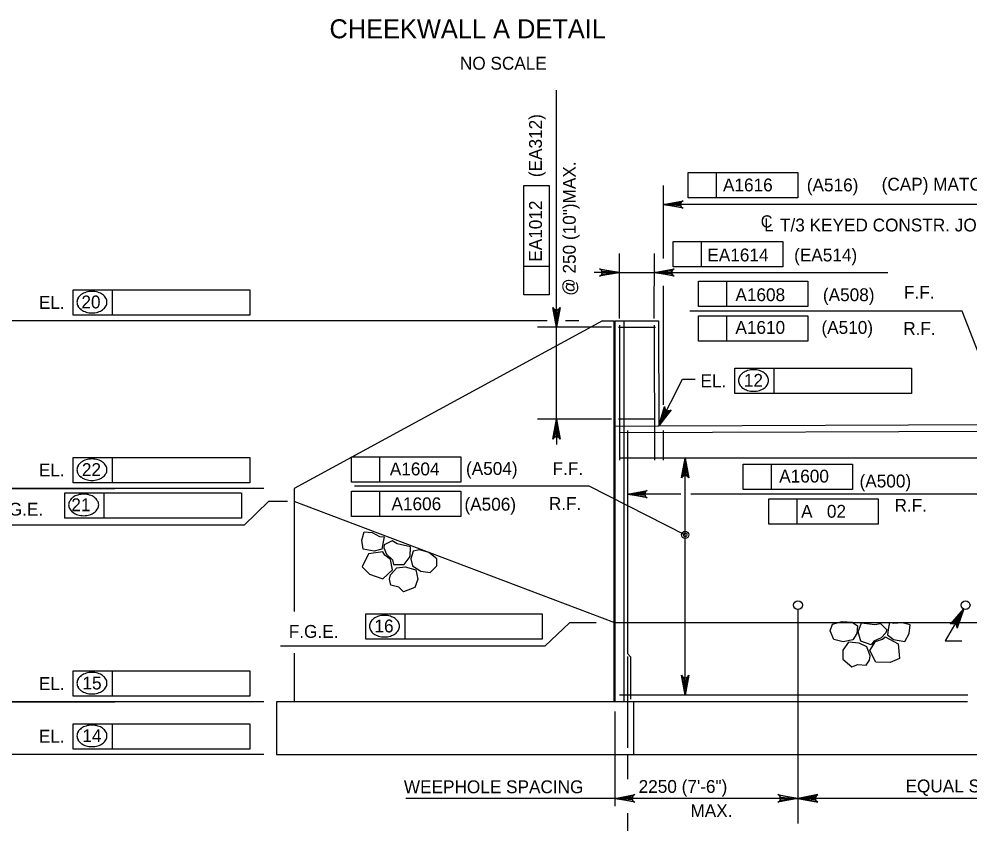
# Model space of a CAD drawing. Extents: x 634540 to 640306, y 296059 to 300275.
# Drawn here: x 638514.3 to 638736.3, y 297928.8 to 298116.7 of the extents above; entities that cross this region are included whole.
import ezdxf

# ---------------------------------------------------------------- set-up
doc = ezdxf.new("R2010")
doc.units = 0
for name, color, linetype in [('1', 7, 'Continuous'), ('10', 7, 'Continuous'), ('3', 7, 'Continuous'), ('4', 7, 'Continuous'), ('5', 7, 'Continuous')]:
    doc.layers.add(name, color=color, linetype=linetype)

# ---------------------------------------------------------------- blocks, each defined once
blk = doc.blocks.new('ROCK')
at = {"layer": '4'}
for points in [[(2.36725, 1.088), (2.2065, 0.82625), (2.378625, 0.506625), (2.66975, 0.3095), (3.128875, 0.403375), (3.48475, 0.6775), (3.4915, 1.123375), (3.25625, 1.36725), (2.783625, 1.308375)], [(1.10175, -0.02725), (1.4015, -0.159125), (1.78825, -0.148875), (1.980875, -0.266), (2.343375, 0.09475), (2.27875, 0.5505), (1.969375, 0.883), (1.4225, 0.553625), (1.152875, 0.479), (1.0105, 0.082)], [(0.74675, 0.359875), (0.882, 0.16), (1.072875, -0.144), (0.892, -0.457375), (0.448125, -0.758625), (0.1, -0.49325), (-0.095, -0.146375), (0.202875, 0.1025), (0.579125, 0.219875)], [(2.231375, -0.71725), (2.2025, -0.266375), (2.45475, 0.037125), (2.9085, 0.28875), (3.2995, 0.047625), (3.46875, -0.344), (3.231625, -0.855), (2.92, -0.860375), (2.5765, -1.054625), (2.340375, -0.904375)], [(1.2085, -0.192875), (0.778375, -0.737625), (1.008375, -1.391375), (1.48725, -1.396875), (2.09825, -1.106625), (2.133375, -0.486375), (1.723125, -0.203375), (1.37425, -0.239875)]]:
    blk.add_lwpolyline(points, close=True, dxfattribs=at)
blk = doc.blocks.new('V')
at = {"layer": '1'}
blk.add_line((0, 0), (0, 0), dxfattribs=at)

msp = doc.modelspace()

# ---------------------------------------------------------------- linework, layer by layer
at = {"layer": '10'}
for p, q in [((638650.47, 298046.26), (638578.54, 298007.13)), ((638650.47, 298046.26), (638653.13, 298046.26)), ((638653.13, 298046.26), (638653.13, 297957.3)), ((638653.35, 298046.26), (638653.35, 297957.3)), ((638653.35, 298046.26), (638663.6, 298046.26)), ((638655.46, 298046.26), (638655.49, 297957.3)), ((638663.6, 298046.26), (638663.63, 298021.71)), ((638663.63, 298021.71), (638880.68, 298022.64)), ((638653.47, 298021.67), (638663.63, 298021.71)), ((638578.54, 298007.13), (638578.54, 297978.4)), ((638653.35, 297975.76), (638578.54, 298004.06)), ((638672.95, 297975.76), (638653.47, 297975.76)), ((638882.32, 297975.76), (638672.95, 297975.76)), ((638578.54, 297968.64), (638578.54, 297957.3)), ((638574.44, 297957.3), (638574.44, 297945)), ((638735.66, 297957.3), (638574.44, 297957.3)), ((638657.74, 297957.3), (638657.74, 297945)), ((638574.44, 297945), (638955.68, 297945))]:
    msp.add_line(p, q, dxfattribs=at)
at = {"layer": '3'}
for p, q in [((638639.77, 298050.63), (638639.77, 298100.09)), ((638670.53, 298080.88), (638696.07, 298080.88)), ((638670.53, 298074.98), (638670.53, 298080.88)), ((638677.13, 298074.98), (638677.13, 298080.88)), ((638696.07, 298080.88), (638696.07, 298074.98)), ((638632.17, 298052.31), (638632.17, 298077.85)), ((638632.17, 298077.85), (638638.07, 298077.85)), ((638638.07, 298077.85), (638638.07, 298052.31)), ((638664.66, 298077.85), (638664.66, 298060.79)), ((638769.74, 298073.41), (638664.66, 298073.41)), ((638696.07, 298074.98), (638670.53, 298074.98)), ((638667.01, 298064.76), (638692.55, 298064.76)), ((638667.01, 298058.86), (638667.01, 298064.76)), ((638673.61, 298058.86), (638673.61, 298064.76)), ((638692.55, 298064.76), (638692.55, 298058.86)), ((638654.46, 298046.77), (638654.49, 298061.95)), ((638662.57, 298046.77), (638662.6, 298061.95)), ((638638.07, 298058.9), (638632.17, 298058.9)), ((638692.55, 298058.86), (638667.01, 298058.86)), ((638654.48, 298057.52), (638648.59, 298057.52)), ((638654.49, 298057.52), (638662.6, 298057.52)), ((638662.59, 298057.52), (638717.09, 298057.52)), ((638665.56, 298057.52), (638668.51, 298057.52)), ((638526.97, 298053.45), (638536.14, 298053.45)), ((638526.97, 298047.54), (638526.97, 298053.45)), ((638536.14, 298047.54), (638536.14, 298053.45)), ((638536.14, 298053.45), (638568.18, 298053.45)), ((638568.18, 298053.45), (638568.18, 298047.54)), ((638664.66, 298054.4), (638664.66, 298026.66)), ((638672.88, 298055.48), (638698.42, 298055.48)), ((638672.88, 298049.57), (638672.88, 298055.48)), ((638679.48, 298049.57), (638679.48, 298055.48)), ((638698.42, 298055.48), (638698.42, 298049.57)), ((638638.07, 298052.31), (638632.17, 298052.31)), ((638639.77, 298047.68), (638639.77, 298050.63)), ((638698.42, 298049.57), (638672.88, 298049.57)), ((638568.18, 298047.54), (638526.97, 298047.54)), ((638734.44, 298048.48), (638670.87, 298048.48)), ((638672.88, 298047.4), (638698.42, 298047.4)), ((638672.88, 298041.49), (638672.88, 298047.4)), ((638679.48, 298041.49), (638679.48, 298047.4)), ((638698.42, 298047.4), (638698.42, 298041.49)), ((638745.29, 298020.52), (638734.44, 298048.48)), ((638637.57, 298046.26), (638483.42, 298046.26)), ((638536.87, 298046.26), (638497.32, 298046.26)), ((638652.58, 298044.72), (638635.34, 298044.72)), ((638639.77, 298023.25), (638639.77, 298044.72)), ((638644.94, 298046.26), (638641.83, 298046.26)), ((638698.42, 298041.49), (638672.88, 298041.49)), ((638681.38, 298035.15), (638690.55, 298035.15)), ((638681.38, 298029.25), (638681.38, 298035.15)), ((638690.55, 298029.25), (638690.55, 298035.15)), ((638690.55, 298035.15), (638722.59, 298035.15)), ((638722.59, 298035.15), (638722.59, 298029.25)), ((638663.63, 298021.71), (638669.19, 298032.64)), ((638669.19, 298032.64), (638672.14, 298032.64)), ((638722.59, 298029.25), (638681.38, 298029.25)), ((638652.58, 298023.25), (638635.34, 298023.25)), ((638639.77, 298020.3), (638639.77, 298017.34)), ((638526.97, 298014.32), (638536.14, 298014.32)), ((638526.97, 298008.42), (638526.97, 298014.32)), ((638536.14, 298008.42), (638536.14, 298014.32)), ((638536.14, 298014.32), (638568.18, 298014.32)), ((638568.18, 298014.32), (638568.18, 298008.42)), ((638591.9, 298014.52), (638617.44, 298014.52)), ((638591.9, 298008.61), (638591.9, 298014.52)), ((638598.5, 298008.61), (638598.5, 298014.52)), ((638617.44, 298014.52), (638617.44, 298008.61)), ((638669.79, 297958.84), (638669.79, 298014.21)), ((638683.35, 298012.78), (638708.88, 298012.78)), ((638683.35, 298006.87), (638683.35, 298012.78)), ((638689.94, 298006.87), (638689.94, 298012.78)), ((638708.88, 298012.78), (638708.88, 298006.87)), ((638571.45, 298007.13), (638492.14, 298007.13)), ((638536.87, 298007.13), (638497.32, 298007.13)), ((638543.27, 298007.13), (638497.32, 298007.13)), ((638501.17, 298007.13), (638536.69, 298007.13)), ((638568.18, 298008.42), (638526.97, 298008.42)), ((638617.44, 298008.61), (638591.9, 298008.61)), ((638592.58, 298007.74), (638647.34, 298007.74)), ((638647.34, 298007.74), (638669.79, 297996.26)), ((638708.88, 298006.87), (638683.35, 298006.87)), ((638525.03, 298000.2), (638525.03, 298006.1)), ((638525.03, 298006.1), (638534.21, 298006.1)), ((638534.21, 298000.2), (638534.21, 298006.1)), ((638534.21, 298006.1), (638566.07, 298006.1)), ((638566.24, 298006.1), (638566.24, 298000.2)), ((638591.9, 298000.53), (638591.9, 298006.44)), ((638591.9, 298006.44), (638617.44, 298006.44)), ((638598.5, 298000.53), (638598.5, 298006.44)), ((638617.44, 298006.44), (638617.44, 298000.53)), ((638668.78, 298005.78), (638656.3, 298005.78)), ((638770.61, 298005.78), (638671.08, 298005.78)), ((638689.34, 297998.79), (638689.34, 298004.69)), ((638689.34, 298004.69), (638714.87, 298004.69)), ((638695.93, 297998.79), (638695.93, 298004.69)), ((638714.87, 298004.69), (638714.87, 297998.79)), ((638572.56, 298004.06), (638566.84, 297998.55)), ((638566.24, 298000.2), (638525.03, 298000.2)), ((638617.44, 298000.53), (638591.9, 298000.53)), ((638566.84, 297998.55), (638505.82, 297998.55)), ((638714.87, 297998.79), (638689.34, 297998.79)), ((638734.83, 297978.99), (638730.48, 297971.5)), ((638595.23, 297977.81), (638604.41, 297977.81)), ((638595.23, 297971.9), (638595.23, 297977.81)), ((638604.41, 297971.9), (638604.41, 297977.81)), ((638604.41, 297977.81), (638636.45, 297977.81)), ((638636.45, 297977.81), (638636.45, 297971.9)), ((638642.76, 297975.76), (638637.05, 297970.26)), ((638649.02, 297975.76), (638642.76, 297975.76)), ((638636.45, 297971.9), (638595.23, 297971.9)), ((638730.48, 297971.5), (638734.35, 297971.5)), ((638637.05, 297970.26), (638575.36, 297970.26)), ((638526.97, 297964.49), (638536.14, 297964.49)), ((638526.97, 297958.59), (638526.97, 297964.49)), ((638536.14, 297958.59), (638536.14, 297964.49)), ((638536.14, 297964.49), (638568.18, 297964.49)), ((638568.18, 297964.49), (638568.18, 297958.59)), ((638568.18, 297958.59), (638526.97, 297958.59)), ((638571.45, 297957.3), (638483.42, 297957.3)), ((638543.27, 297957.3), (638497.32, 297957.3)), ((638501.17, 297957.3), (638536.69, 297957.3)), ((638653.35, 297955.05), (638653.35, 297932.9)), ((638526.97, 297952.19), (638536.14, 297952.19)), ((638526.97, 297946.28), (638526.97, 297952.19)), ((638536.14, 297946.28), (638536.14, 297952.19)), ((638536.14, 297952.19), (638568.18, 297952.19)), ((638568.18, 297952.19), (638568.18, 297946.28)), ((638571.45, 297945), (638483.42, 297945)), ((638568.18, 297946.28), (638526.97, 297946.28)), ((638656.3, 297945), (638656.3, 297939.23)), ((638885.79, 297934.76), (638604.59, 297934.76)), ((638656.3, 297931.32), (638656.3, 297916.35))]:
    msp.add_line(p, q, dxfattribs=at)
for points in [[(638664.66, 298073.41), (638669.32, 298074.28), (638668.96, 298074.03), (638668.77, 298073.72), (638668.72, 298073.41), (638668.77, 298073.09), (638668.96, 298072.78), (638669.32, 298072.53), (638664.66, 298073.41), (638668.96, 298072.78), (638668.77, 298073.09), (638664.66, 298073.41), (638668.72, 298073.41), (638668.77, 298073.72), (638664.66, 298073.41), (638668.96, 298074.03)], [(638654.48, 298057.52), (638649.82, 298056.64), (638650.18, 298056.89), (638650.37, 298057.21), (638650.42, 298057.52), (638650.37, 298057.83), (638650.18, 298058.14), (638649.82, 298058.39), (638654.48, 298057.52), (638650.18, 298058.14), (638650.37, 298057.83), (638654.48, 298057.52), (638650.42, 298057.52), (638650.37, 298057.21), (638654.48, 298057.52), (638650.18, 298056.89)], [(638662.59, 298057.52), (638667.25, 298058.39), (638666.9, 298058.14), (638666.71, 298057.83), (638666.66, 298057.52), (638666.71, 298057.21), (638666.9, 298056.89), (638667.25, 298056.64), (638662.59, 298057.52), (638666.9, 298056.89), (638666.71, 298057.21), (638662.59, 298057.52), (638666.66, 298057.52), (638666.71, 298057.83), (638662.59, 298057.52), (638666.9, 298058.14)], [(638639.77, 298044.72), (638638.9, 298049.38), (638639.15, 298049.03), (638639.46, 298048.84), (638639.77, 298048.79), (638640.08, 298048.84), (638640.4, 298049.03), (638640.65, 298049.38), (638639.77, 298044.72), (638640.4, 298049.03), (638640.08, 298048.84), (638639.77, 298044.72), (638639.77, 298048.79), (638639.46, 298048.84), (638639.77, 298044.72), (638639.15, 298049.03)], [(638663.63, 298021.71), (638664.97, 298026.26), (638665.03, 298025.83), (638665.22, 298025.52), (638665.47, 298025.34), (638665.78, 298025.24), (638666.14, 298025.26), (638666.52, 298025.47), (638663.63, 298021.71), (638666.14, 298025.26), (638665.78, 298025.24), (638663.63, 298021.71), (638665.47, 298025.34), (638665.22, 298025.52), (638663.63, 298021.71), (638665.03, 298025.83)], [(638639.77, 298023.25), (638640.65, 298018.59), (638640.4, 298018.95), (638640.08, 298019.13), (638639.77, 298019.18), (638639.46, 298019.13), (638639.15, 298018.95), (638638.9, 298018.59), (638639.77, 298023.25), (638639.15, 298018.95), (638639.46, 298019.13), (638639.77, 298023.25), (638639.77, 298019.18), (638640.08, 298019.13), (638639.77, 298023.25), (638640.4, 298018.95)], [(638669.79, 298014.21), (638670.66, 298009.55), (638670.42, 298009.91), (638670.1, 298010.09), (638669.79, 298010.15), (638669.48, 298010.09), (638669.17, 298009.91), (638668.92, 298009.55), (638669.79, 298014.21), (638669.17, 298009.91), (638669.48, 298010.09), (638669.79, 298014.21), (638669.79, 298010.15), (638670.1, 298010.09), (638669.79, 298014.21), (638670.42, 298009.91)], [(638656.3, 298005.78), (638660.96, 298006.65), (638660.6, 298006.4), (638660.42, 298006.09), (638660.37, 298005.78), (638660.42, 298005.47), (638660.6, 298005.15), (638660.96, 298004.9), (638656.3, 298005.78), (638660.6, 298005.15), (638660.42, 298005.47), (638656.3, 298005.78), (638660.37, 298005.78), (638660.42, 298006.09), (638656.3, 298005.78), (638660.6, 298006.4)], [(638734.83, 297978.99), (638733.25, 297974.52), (638733.21, 297974.96), (638733.03, 297975.28), (638732.79, 297975.48), (638732.49, 297975.59), (638732.13, 297975.59), (638731.73, 297975.4), (638734.83, 297978.99), (638732.13, 297975.59), (638732.49, 297975.59), (638734.83, 297978.99), (638732.79, 297975.48), (638733.03, 297975.28), (638734.83, 297978.99), (638733.21, 297974.96)], [(638669.79, 297958.84), (638668.92, 297963.5), (638669.17, 297963.14), (638669.48, 297962.96), (638669.79, 297962.91), (638670.1, 297962.96), (638670.42, 297963.14), (638670.66, 297963.5), (638669.79, 297958.84), (638670.42, 297963.14), (638670.1, 297962.96), (638669.79, 297958.84), (638669.79, 297962.91), (638669.48, 297962.96), (638669.79, 297958.84), (638669.17, 297963.14)]]:
    msp.add_lwpolyline(points, dxfattribs=at)
for points in [[(638651.54, 298058.01), (638651.54, 298057.03), (638654.49, 298057.52)], [(638665.56, 298058.01), (638665.56, 298057.03), (638662.6, 298057.52)], [(638639.28, 298047.68), (638640.27, 298047.68), (638639.77, 298044.72)], [(638664.53, 298024.57), (638665.41, 298024.12), (638663.63, 298021.71)], [(638639.28, 298020.3), (638640.27, 298020.3), (638639.77, 298023.25)], [(638670.28, 298011.26), (638669.3, 298011.26), (638669.79, 298014.21)], [(638733.78, 297976.21), (638732.93, 297976.7), (638734.84, 297979.01)], [(638670.28, 297961.8), (638669.3, 297961.8), (638669.79, 297958.84)]]:
    msp.add_lwpolyline(points, close=True, dxfattribs=at)
for centre, radius in [((638669.79, 297996.26), 0.833), ((638669.79, 297996.26), 0.417), ((638696.12, 297979.86), 1.03), ((638735.24, 297979.86), 1.03)]:
    msp.add_circle(centre, radius, dxfattribs=at)
for centre, radius, start, end in [((638529.67, 298050.6), 1.83, 149.9767, 180), ((638530.47, 298050.14), 2.76, 125.6316, 149.9767), ((638531, 298049.4), 3.66, 106.5358, 125.6316), ((638531.35, 298048.24), 4.87, 90, 106.5358), ((638531.35, 298048.24), 4.87, 73.4642, 90), ((638531.69, 298049.4), 3.66, 54.3684, 73.4642), ((638532.22, 298050.14), 2.76, 30.0233, 54.3684), ((638533.02, 298050.6), 1.83, 0, 30.0233), ((638529.67, 298050.6), 1.83, 180, 210.0233), ((638530.47, 298051.07), 2.76, 210.0233, 234.3684), ((638532.22, 298051.07), 2.76, 305.6316, 329.9767), ((638533.02, 298050.6), 1.83, 329.9767, 0), ((638531, 298051.8), 3.66, 234.3684, 253.4642), ((638531.35, 298052.96), 4.87, 253.4642, 270), ((638531.35, 298052.96), 4.87, 270, 286.5358), ((638531.69, 298051.8), 3.66, 286.5358, 305.6316), ((638684.88, 298031.84), 2.76, 125.6316, 149.9767), ((638685.41, 298031.11), 3.66, 106.5358, 125.6316), ((638685.76, 298029.95), 4.87, 90, 106.5358), ((638685.76, 298029.95), 4.87, 73.4642, 90), ((638686.1, 298031.11), 3.66, 54.3684, 73.4642), ((638686.63, 298031.84), 2.76, 30.0233, 54.3684), ((638684.08, 298032.31), 1.83, 149.9767, 180), ((638684.08, 298032.31), 1.83, 180, 210.0233), ((638684.88, 298032.77), 2.76, 210.0233, 234.3684), ((638686.63, 298032.77), 2.76, 305.6316, 329.9767), ((638687.43, 298032.31), 1.83, 0, 30.0233), ((638687.43, 298032.31), 1.83, 329.9767, 0), ((638685.41, 298033.51), 3.66, 234.3684, 253.4642), ((638685.76, 298034.67), 4.87, 253.4642, 270), ((638685.76, 298034.67), 4.87, 270, 286.5358), ((638686.1, 298033.51), 3.66, 286.5358, 305.6316), ((638531, 298010.28), 3.66, 106.5358, 125.6316), ((638531.35, 298009.12), 4.87, 90, 106.5358), ((638531.35, 298009.12), 4.87, 73.4642, 90), ((638531.69, 298010.28), 3.66, 54.3684, 73.4642), ((638529.67, 298011.48), 1.83, 149.9767, 180), ((638529.67, 298011.48), 1.83, 180, 210.0233), ((638530.47, 298011.01), 2.76, 125.6316, 149.9767), ((638532.22, 298011.01), 2.76, 30.0233, 54.3684), ((638533.02, 298011.48), 1.83, 0, 30.0233), ((638533.02, 298011.48), 1.83, 329.9767, 0), ((638530.47, 298011.94), 2.76, 210.0233, 234.3684), ((638531, 298012.68), 3.66, 234.3684, 253.4642), ((638531.35, 298013.84), 4.87, 253.4642, 270), ((638531.35, 298013.84), 4.87, 270, 286.5358), ((638531.69, 298012.68), 3.66, 286.5358, 305.6316), ((638532.22, 298011.94), 2.76, 305.6316, 329.9767), ((638528.54, 298002.79), 2.76, 125.6316, 149.9767), ((638529.07, 298002.06), 3.66, 106.5358, 125.6316), ((638529.41, 298000.9), 4.87, 90, 106.5358), ((638529.41, 298000.9), 4.87, 73.4642, 90), ((638529.75, 298002.06), 3.66, 54.3684, 73.4642), ((638530.28, 298002.79), 2.76, 30.0233, 54.3684), ((638527.73, 298003.26), 1.83, 149.9767, 180), ((638527.73, 298003.26), 1.83, 180, 210.0233), ((638531.09, 298003.26), 1.83, 0, 30.0233), ((638531.09, 298003.26), 1.83, 329.9767, 0), ((638528.54, 298003.72), 2.76, 210.0233, 234.3684), ((638529.07, 298004.46), 3.66, 234.3684, 253.4642), ((638529.41, 298005.62), 4.87, 253.4642, 270), ((638529.41, 298005.62), 4.87, 270, 286.5358), ((638529.75, 298004.46), 3.66, 286.5358, 305.6316), ((638530.28, 298003.72), 2.76, 305.6316, 329.9767), ((638597.94, 297974.96), 1.83, 149.9767, 180), ((638598.74, 297974.49), 2.76, 125.6316, 149.9767), ((638599.27, 297973.76), 3.66, 106.5358, 125.6316), ((638599.61, 297972.6), 4.87, 90, 106.5358), ((638599.61, 297972.6), 4.87, 73.4642, 90), ((638599.96, 297973.76), 3.66, 54.3684, 73.4642), ((638600.48, 297974.49), 2.76, 30.0233, 54.3684), ((638601.29, 297974.96), 1.83, 0, 30.0233), ((638597.94, 297974.96), 1.83, 180, 210.0233), ((638598.74, 297975.42), 2.76, 210.0233, 234.3684), ((638600.48, 297975.42), 2.76, 305.6316, 329.9767), ((638601.29, 297974.96), 1.83, 329.9767, 0), ((638599.27, 297976.16), 3.66, 234.3684, 253.4642), ((638599.61, 297977.32), 4.87, 253.4642, 270), ((638599.61, 297977.32), 4.87, 270, 286.5358), ((638599.96, 297976.16), 3.66, 286.5358, 305.6316), ((638529.67, 297961.65), 1.83, 149.9767, 180), ((638530.47, 297961.18), 2.76, 125.6316, 149.9767), ((638531, 297960.45), 3.66, 106.5358, 125.6316), ((638531.35, 297959.29), 4.87, 90, 106.5358), ((638531.35, 297959.29), 4.87, 73.4642, 90), ((638531.69, 297960.45), 3.66, 54.3684, 73.4642), ((638532.22, 297961.18), 2.76, 30.0233, 54.3684), ((638533.02, 297961.65), 1.83, 0, 30.0233), ((638529.67, 297961.65), 1.83, 180, 210.0233), ((638530.47, 297962.11), 2.76, 210.0233, 234.3684), ((638532.22, 297962.11), 2.76, 305.6316, 329.9767), ((638533.02, 297961.65), 1.83, 329.9767, 0), ((638531, 297962.85), 3.66, 234.3684, 253.4642), ((638531.35, 297964.01), 4.87, 253.4642, 270), ((638531.35, 297964.01), 4.87, 270, 286.5358), ((638531.69, 297962.85), 3.66, 286.5358, 305.6316), ((638531, 297948.14), 3.66, 106.5358, 125.6316), ((638531.35, 297946.98), 4.87, 90, 106.5358), ((638531.35, 297946.98), 4.87, 73.4642, 90), ((638531.69, 297948.14), 3.66, 54.3684, 73.4642), ((638529.67, 297949.34), 1.83, 149.9767, 180), ((638529.67, 297949.34), 1.83, 180, 210.0233), ((638530.47, 297948.88), 2.76, 125.6316, 149.9767), ((638532.22, 297948.88), 2.76, 30.0233, 54.3684), ((638533.02, 297949.34), 1.83, 0, 30.0233), ((638533.02, 297949.34), 1.83, 329.9767, 0), ((638530.47, 297949.81), 2.76, 210.0233, 234.3684), ((638531, 297950.54), 3.66, 234.3684, 253.4642), ((638531.35, 297951.7), 4.87, 253.4642, 270), ((638531.35, 297951.7), 4.87, 270, 286.5358), ((638531.69, 297950.54), 3.66, 286.5358, 305.6316), ((638532.22, 297949.81), 2.76, 305.6316, 329.9767)]:
    msp.add_arc(centre, radius, start, end, dxfattribs=at)
at = {"layer": '4'}
msp.add_line((638577, 298004.06), (638572.56, 298004.06), dxfattribs=at)
for points in [[(638653.35, 297934.76), (638658.01, 297935.64), (638657.65, 297935.39), (638657.47, 297935.07), (638657.41, 297934.76), (638657.47, 297934.45), (638657.65, 297934.14), (638658.01, 297933.89), (638653.35, 297934.76), (638657.65, 297934.14), (638657.47, 297934.45), (638653.35, 297934.76), (638657.41, 297934.76), (638657.47, 297935.07), (638653.35, 297934.76), (638657.65, 297935.39)], [(638696.11, 297934.76), (638691.45, 297933.89), (638691.81, 297934.14), (638692, 297934.45), (638692.05, 297934.76), (638692, 297935.07), (638691.81, 297935.39), (638691.45, 297935.64), (638696.11, 297934.76), (638691.81, 297935.39), (638692, 297935.07), (638696.11, 297934.76), (638692.05, 297934.76), (638692, 297934.45), (638696.11, 297934.76), (638691.81, 297934.14)], [(638696.11, 297934.76), (638700.78, 297933.89), (638700.42, 297934.14), (638700.23, 297934.45), (638700.18, 297934.76), (638700.23, 297935.07), (638700.42, 297935.39), (638700.78, 297935.64), (638696.11, 297934.76), (638700.42, 297935.39), (638700.23, 297935.07), (638696.11, 297934.76), (638700.18, 297934.76), (638700.23, 297934.45), (638696.11, 297934.76), (638700.42, 297934.14)]]:
    msp.add_lwpolyline(points, dxfattribs=at)
at = {"layer": '5'}
for p, q in [((638654.2, 298044.72), (638662.83, 298044.72)), ((638654.46, 298045.24), (638654.49, 298013.7)), ((638662.57, 298045.24), (638662.6, 298013.7)), ((638662.79, 298023.25), (638654.24, 298023.25)), ((638654.49, 298020.14), (638773.18, 298020.64)), ((638656.3, 298020.65), (638656.3, 297968.55)), ((638664.66, 298020.65), (638664.66, 298013.7)), ((638773.17, 298014.21), (638654.49, 298014.21)), ((638696.11, 297978.84), (638696.11, 297928.9)), ((638656.3, 297968.55), (638657.04, 297967.82)), ((638656.3, 297967.85), (638656.3, 297946.54)), ((638657.04, 297967.82), (638657.04, 297957.88)), ((638735.74, 297958.84), (638654.49, 297958.84))]:
    msp.add_line(p, q, dxfattribs=at)

# ---------------------------------------------------------------- block references
at = {"layer": '3', "xscale": 0.78743606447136, "yscale": 0.78743606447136}
for p in [(638550.28, 298014.41), (638550.14, 298006.1)]:
    msp.add_blockref('V', p, dxfattribs=at)
at = {"layer": '3', "xscale": 4.921475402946}
for p, yscale, rotation in [((638595.69, 297997.14), 4.921475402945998, -44.503733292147), ((638721.56, 297975.7), -4.921475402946, -156.2166383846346)]:
    msp.add_blockref('ROCK', p, dxfattribs=dict(at, yscale=yscale, rotation=rotation))

# ---------------------------------------------------------------- texts
at = {"layer": '3'}
for s, height, p in [('CHEEKWALL A DETAIL', 4.4294, (638586.78, 298112.2)), ('NO SCALE', 3, (638617.22, 298104.87)), ('A1616', 3, (638678.62, 298076.46)), ('(A516)', 3, (638698.18, 298076.46)), ('(CAP) MATCH R.F.', 3.0001, (638715.65, 298076.63)), ('C', 2.84, (638687.42, 298068.03)), ('L', 3, (638688.22, 298067.14)), ('T/3 KEYED CONSTR. JOINT', 3.0001, (638691.92, 298067.1)), ('EA1614', 3, (638674.97, 298060.11)), ('(EA514)', 3, (638695.22, 298060.11)), ('A1608', 3, (638681.52, 298050.83)), ('(A508)', 3, (638701.94, 298050.83)), ('F.F.', 3, (638720.86, 298051.39)), ('EL.', 3, (638518.95, 298049.02)), ('20', 3, (638528.88, 298049.14)), ('A1610', 3, (638681.52, 298043.2)), ('(A510)', 3, (638701.6, 298043.2)), ('R.F.', 3, (638720.68, 298042.96)), ('EL.', 3, (638673.36, 298030.73)), ('12', 3, (638683.49, 298030.84)), ('EL.', 3, (638518.95, 298009.9)), ('22', 3, (638528.99, 298010.01)), ('A1604', 3, (638600.86, 298010.16)), ('(A504)', 3, (638618.64, 298010.27)), ('F.F.', 3, (638638.84, 298010.24)), ('A1600', 3, (638691.74, 298008.49)), ('(A500)', 3, (638710.49, 298007.34)), ('21', 3, (638526.53, 298001.79)), ('A1606', 3, (638601.25, 298002.02)), ('(A506)', 3, (638618.28, 298001.92)), ('R.F.', 3, (638637.98, 298002.09)), ('R.F.', 3, (638718.65, 298001.67)), ('F.G.E.', 3, (638508.36, 298000.76)), ('A   02', 3, (638696.85, 298000.27)), ('16', 3, (638597.28, 297973.5)), ('F.G.E.', 3, (638577.28, 297972.23)), ('EL.', 3, (638518.95, 297960.07)), ('15', 3, (638529.13, 297960.18)), ('EL.', 3, (638518.95, 297947.76)), ('14', 3, (638529.1, 297947.88)), ('WEEPHOLE SPACING', 3.0001, (638604.14, 297935.96)), ('2250 (7\'-6")', 3.0001, (638658.93, 297936.04)), ('EQUAL SPACES @ 2250 (7\'-6") MAX.', 3.0001, (638721.22, 297936.15)), ('MAX.', 3, (638671.02, 297930.39))]:
    msp.add_text(s, height=height, dxfattribs=at).set_placement(p)
for s, height, p in [('(EA312)', 3, (638636.36, 298079.78)), ('@ 250 (10")MAX.', 3.0001, (638644.25, 298052.09)), ('EA1012', 3, (638636.36, 298060.04))]:
    msp.add_text(s, height=height, rotation=90, dxfattribs=at).set_placement(p)

doc.saveas('drawing.dxf')
